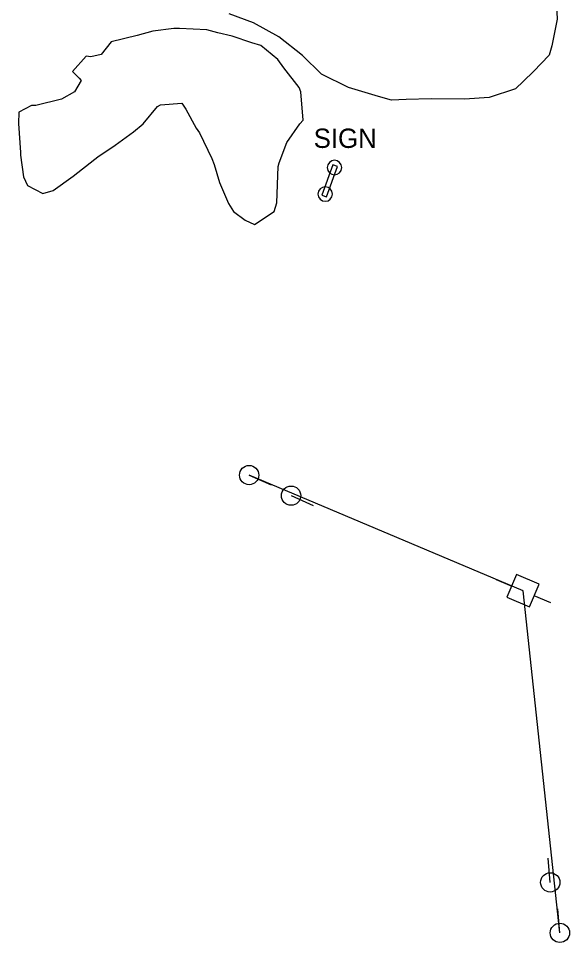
# Model space of a CAD drawing. Extents: x 2160437 to 2172832, y 205694 to 212444.
# Drawn here: x 2167051.3 to 2167165.5, y 208664.3 to 208855.7 of the extents above; entities that cross this region are included whole.
import ezdxf

# ---------------------------------------------------------------- set-up
doc = ezdxf.new("R2010")
doc.units = 0
for name, color, linetype in [('Default', 7, 'Continuous'), ('RD_EX_Bldg_Signs', 7, 'Continuous'), ('RD_EX_BldgApp_txCode', 7, 'Continuous'), ('RD_EX_Road_Post', 7, 'Continuous'), ('RD_EX_UT', 7, 'Continuous'), ('RD_EX_UT_Guy', 7, 'Continuous'), ('RD_EX_VEG_ShrubLine', 7, 'Continuous'), ('RD_EX_VEG_TreeLine', 7, 'Continuous')]:
    doc.layers.add(name, color=color, linetype=linetype)

# ---------------------------------------------------------------- blocks, each defined once
blk = doc.blocks.new('POST')
at = {"layer": 'Default'}
for start, end in [(90, 270), (270, 90)]:
    blk.add_arc((0, 0), 0.0417, start, end, dxfattribs=at)
blk = doc.blocks.new('PP')
at = {"layer": 'RD_EX_UT'}
for p, q in [((2.49, 2.51), (-2.51, 2.51)), ((-2.51, 2.51), (-2.51, -2.49)), ((2.49, -2.49), (2.49, 2.51)), ((-5.94, -0.05), (-2.47, -0.05)), ((2.42, -0.05), (6.06, -0.05)), ((-2.51, -2.49), (2.49, -2.49))]:
    blk.add_line(p, q, dxfattribs=at)

msp = doc.modelspace()

# ---------------------------------------------------------------- linework, layer by layer
at = {"layer": 'RD_EX_Bldg_Signs'}
msp.add_lwpolyline([(2167116.38, 208825.35), (2167114.13, 208819.11), (2167115.13, 208818.75), (2167117.38, 208824.99)], close=True, dxfattribs=at)
at = {"layer": 'RD_EX_UT'}
for p, q in [((2167099.07, 208761.11), (2167103.65, 208759.11)), ((2167107.76, 208756.85), (2167112.33, 208754.82)), ((2167161.47, 208676.76), (2167161.01, 208681.74)), ((2167163.47, 208666.3), (2167163.05, 208671.28))]:
    msp.add_line(p, q, dxfattribs=at)
for centre in [(2167099.07, 208761.11), (2167107.76, 208756.85), (2167161.47, 208676.76), (2167163.47, 208666.3)]:
    msp.add_circle(centre, 2, dxfattribs=at)
at = {"layer": 'RD_EX_UT_Guy'}
for points in [[(2167155.83, 208737.15), (2167099.07, 208761.11)], [(2167163.47, 208666.3), (2167155.83, 208737.15)]]:
    msp.add_lwpolyline(points, dxfattribs=at)
at = {"layer": 'RD_EX_VEG_ShrubLine'}
msp.add_lwpolyline([(2167070.48, 208850.87), (2167068.4, 208848.2), (2167066.25, 208847.74), (2167065.31, 208847.86), (2167062.43, 208844.68), (2167063.81, 208843.31), (2167064.23, 208842.86), (2167062.9, 208840.48), (2167060.16, 208838.98), (2167054.88, 208837.64), (2167053.94, 208837.63), (2167051.32, 208836.26), (2167051.26, 208833.93), (2167051.66, 208827.95), (2167051.65, 208827.39), (2167052.33, 208822.85), (2167053.11, 208821.12), (2167056.32, 208819.42), (2167058.43, 208820.08), (2167062.58, 208823.05), (2167067.1, 208826.55), (2167067.74, 208827), (2167071.28, 208829.44), (2167075.09, 208832.2), (2167077.13, 208833.83), (2167080.09, 208837.47), (2167080.67, 208837.77), (2167085.15, 208838.16), (2167085.95, 208836.92), (2167088.08, 208832.97), (2167088.78, 208832.03), (2167091.34, 208826.69), (2167091.82, 208825.41), (2167092.94, 208821.72), (2167094.76, 208817.35), (2167095.81, 208815.68), (2167098.24, 208813.9), (2167100.15, 208813.03), (2167104.24, 208815.72), (2167104.81, 208817.52), (2167105.11, 208825.04), (2167105.26, 208825.79), (2167106.85, 208829.98), (2167109.55, 208833.87), (2167110.26, 208834.6), (2167109.76, 208840.5), (2167109.42, 208841.4), (2167106.28, 208845.45), (2167105.02, 208847.21), (2167101.46, 208850.07), (2167099.66, 208850.64), (2167095.55, 208852.01), (2167092.57, 208852.73), (2167090.29, 208853.33), (2167084.62, 208853.6), (2167083.43, 208853.58), (2167079.13, 208853.04), (2167075.86, 208852.16)], close=True, dxfattribs=at)
at = {"layer": 'RD_EX_VEG_TreeLine'}
msp.add_lwpolyline([(2167162.63, 208861.58), (2167162.93, 208855.52), (2167161.79, 208850), (2167161.28, 208848.05), (2167158.02, 208844.73), (2167155.92, 208842.69), (2167154.27, 208841.13), (2167148.83, 208839.3), (2167143.69, 208838.96), (2167143.69, 208838.96), (2167136.76, 208839.06), (2167131.64, 208838.89), (2167128.57, 208838.73), (2167125.87, 208839.51), (2167119.69, 208841.39), (2167114.07, 208844.13), (2167114.07, 208844.13), (2167110.12, 208848.04), (2167105.2, 208851.9), (2167105.2, 208851.9), (2167099.97, 208854.77), (2167094.9, 208856.64)], dxfattribs=at)

# ---------------------------------------------------------------- block references
at = {"layer": 'RD_EX_Road_Post', "xscale": 36, "yscale": 36}
for p in [(2167116.76, 208824.8), (2167114.83, 208819.32)]:
    msp.add_blockref('POST', p, dxfattribs=at)
at = {"layer": 'RD_EX_UT', "xscale": 1.02, "yscale": 1.0199999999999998, "rotation": -22.98747800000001}
msp.add_blockref('PP', (2167155.83, 208737.15), dxfattribs=at)

# ---------------------------------------------------------------- texts
at = {"layer": 'RD_EX_BldgApp_txCode'}
msp.add_text('SIGN', height=4, dxfattribs=at).set_placement((2167112.44, 208828.87))

doc.saveas('drawing.dxf')
